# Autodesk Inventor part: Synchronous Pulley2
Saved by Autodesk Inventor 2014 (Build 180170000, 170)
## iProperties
Created: 2013-12
Part Number: Synchronous Pulley2
Material: Steel
Document SubType Name: Modeling
Designer: Bram
Density: 1 g/cm^3
Appearance: Steel
CustomPartVersion: 1
Author: Bram
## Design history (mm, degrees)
sketch "Pulley Sketch"
  geometry: L1 (-0.643, 2.91)-(-0.419, 2.294); L2 (-0.419, 2.294)-(0.419, 2.294); L3 (0.419, 2.294)-(0.643, 2.91); L4 (0, 0)-(0, 2.98); C1 r 3.234 at (0, 0); A1 r 2.98 centre (0, 0) between (-0.643, 2.91) and (0.643, 2.91); 2 further points
  constraints: 8 end point, 3 coincident, 3 point on circle, 2 centre point, 1 horizontal, 1 midpoint, 1 point on line, 1 vertical, 1 vertical alignment, 3 other
  dimensions: "d0" = 6.46806 diameter of C1 (computed from da_pb, da_z); "d1" = 0.254 radial gap between concentric circles of C1 A1 (= da_a); "d2" = 0.6858 dimension on A1 (= da_hg); "d3" = 40 deg angle of L3 L1 (= 2 x da_fi); "d4" = 0.8382 distance of L1.end L2.end (= da_bw)
extrude "Base Body" new body sketch "Pulley Sketch" stored distance "d5" = 7.112 (= da_bf); taper "d6" = 0 deg
extrude "Tooth" cut sketch "Pulley Sketch" stored distance "d7" = 7.112 (= da_bf); taper "d8" = 0 deg
fillet "Tooth Fillet" dims "d9" = 0.254 (= da_rb), "d10" = 0.127 (= da_rt)
pattern_circular "Teeth" dims angle "d12" = 360 deg
feature "Left flange"
feature "Right flange"
body "Solid1"
other parameters: "da_pb" = 2.032 [user parameter; used in 1 equation term], "da_fi" = 20 deg [user parameter; used in 1 equation term], "da_hg" = 0.6858 [user parameter; used in 1 equation term], "da_bw" = 0.8382 [user parameter; used in 1 equation term], "da_rb" = 0.254 [user parameter; used in 1 equation term], "da_rt" = 0.127 [user parameter; used in 1 equation term], "da_a" = 0.254 [user parameter; used in 3 equation terms], "da_bf" = 7.112 [user parameter; used in 2 equation terms], "d15" = 0, "da_wf" = 0.5842 [user parameter; used in 2 equation terms], "da_hf" = 0.508 [user parameter; used in 2 equation terms], "d16" = 0
